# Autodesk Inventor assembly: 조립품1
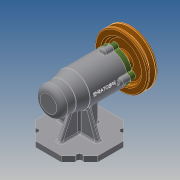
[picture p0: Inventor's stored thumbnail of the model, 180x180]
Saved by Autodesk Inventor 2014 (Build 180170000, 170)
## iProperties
Created: 2019-12
Part Number: 조립품1
Document SubType Name: Assembly
Designer: kb542-15
Author: kb542-15
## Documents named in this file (12)
- C:\Users\kb542-15\Desktop\491204V1061\조립품1.iam
- C:\Users\kb542-15\Desktop\491204V1061\본체.ipt
- C:\Users\kb542-15\Desktop\491204V1061\커버.ipt
- C:\Users\kb542-15\Desktop\491204V1061\축.ipt
- C:\Users\kb542-15\Desktop\491204V1061\베어링 6004.ipt
- C:\Users\kb542-15\Desktop\491204V1061\어댑터슬리브.ipt
- C:\Users\kb542-15\Desktop\491204V1061\베어링 51202.ipt
- C:\Users\kb542-15\Desktop\491204V1061\볼트 M4.ipt
- C:\Users\kb542-15\Desktop\491204V1061\오일 실.ipt
- C:\Users\kb542-15\Desktop\491204V1061\키 5 x 5 x 16.ipt
- C:\Users\kb542-15\Desktop\491204V1061\V벨트풀리.ipt
- C:\Users\kb542-15\Desktop\491204V1061\멈춤나사 M3.ipt
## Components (1 placed, 1 different names)
1. V벨트풀리:1
